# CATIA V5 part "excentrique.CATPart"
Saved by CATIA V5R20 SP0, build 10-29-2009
Part number: excentrique
Bounding box of the stored display mesh (mm): x 0 to 10, y 92.5 to 107.5, z -7.312 to 7.312
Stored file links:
  C:\Users\Julien\Desktop\IAO_Mecanisme_991_v2\Assemblage\excentrique.CATPart
  C:\Users\Julien\Desktop\IAO_Mecanisme_991_v2\Assemblage\Ass_IAO_991_skl.CATProduct
  C:\Users\Julien\Desktop\IAO_Mecanisme_991_v2\Assemblage\rainure_circulaire.CATPart
  C:\Users\Julien\Desktop\IAO_Mecanisme_991_v2\Assemblage\bati.CATPart
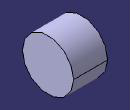
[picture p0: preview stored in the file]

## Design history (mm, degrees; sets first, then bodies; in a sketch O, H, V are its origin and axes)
Set1
  DatumSurface1: linked copy from another document
  DatumPoint1: linked copy from another document
  DatumSurface2: linked copy from another document
Body1 (main body)
  Sketch1 on face of DatumSurface1, origin (10, 0, 0), H (0, -1, 0), V (0, 0, 1)
    circle A1 centre (-100, 0) radius 7.5
    point P1 (-100, 0)
    reference projected point E1 (-100, 0) from DatumPoint1
    radius A1 = 7.5
    coincidence: P1 E1
  Pad1: profile Sketch1, direction (-1, 0, 0), up to face of DatumSurface2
